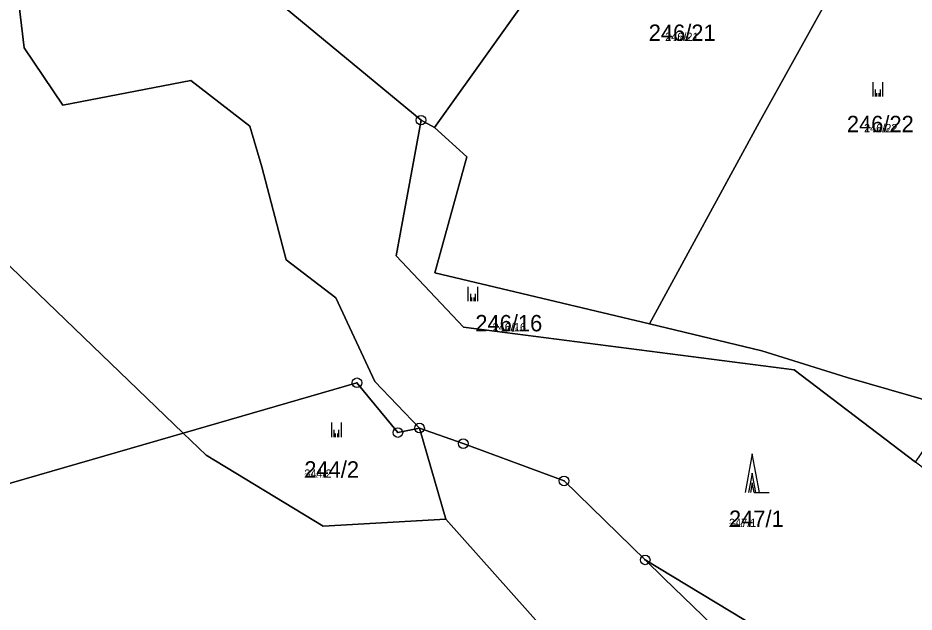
# Model space of a CAD drawing. Extents: x -759873 to -758487, y -975024 to -973516.
# Drawn here: x -759165.8 to -759072.7, y -974638.1 to -974576.4 of the extents above; entities that cross this region are included whole.
import ezdxf

# ---------------------------------------------------------------- set-up
doc = ezdxf.new("R2010")
doc.units = 0
for name, color, linetype in [('KAT_02_hranice parcel', 7, 'Continuous'), ('KAT_03_1000_čísla parcelní', 7, 'Continuous'), ('KAT_03_250_čísla parcelní', 7, 'Continuous'), ('KAT_03_500_čísla parcelní', 7, 'Continuous'), ('KAT_05_1000_značky kultur', 7, 'Continuous'), ('KAT_05_250_značky kultur', 7, 'Continuous'), ('KAT_05_500_značky kultur', 7, 'Continuous'), ('KAT_11_značky bodu BP', 7, 'Continuous'), ('KAT_14_plocha_pozemek', 7, 'Continuous')]:
    doc.layers.add(name, color=color, linetype=linetype)

msp = doc.modelspace()

# ---------------------------------------------------------------- linework, layer by layer
at = {"layer": 'KAT_02_hranice parcel'}
for p, q in [((-759123.88, -974586.97), (-759138.78, -974574.64)), ((-759122.47, -974587.73), (-759123.88, -974586.97)), ((-759181.41, -974628.97), (-759148.58, -974619.46)), ((-759121.31, -974628.39), (-759124.04, -974618.94))]:
    msp.add_line(p, q, dxfattribs=at)
for points in [[(-759124.04, -974618.94), (-759128.67, -974614.12), (-759132.72, -974605.42), (-759137.89, -974601.46), (-759140.41, -974591.83), (-759141.66, -974587.58), (-759147.81, -974582.84), (-759161.09, -974585.41), (-759165.12, -974579.47), (-759166.21, -974570.14), (-759161.85, -974571.03), (-759164.75, -974552.56), (-759173.97, -974541.64), (-759175.43, -974540.05), (-759178.37, -974531.68), (-759179.47, -974515.71), (-759177.07, -974506.79), (-759176.34, -974497.63), (-759172.37, -974482.45)], [(-759122.47, -974587.73), (-759110.32, -974570.69), (-759106.9, -974566.95), (-759100.94, -974559.67), (-759093.17, -974549.44), (-759087, -974539.27)], [(-759100.16, -974608.12), (-759088.78, -974587.22), (-759079.24, -974570.06), (-759074.96, -974563.7), (-759067.83, -974550.62)], [(-759217.96, -974564.68), (-759183.74, -974565.93), (-759174.05, -974595), (-759148.58, -974619.46)], [(-759072.53, -974622.47), (-759085.12, -974612.91), (-759119.49, -974608.48), (-759126.45, -974601.07), (-759123.88, -974586.97)], [(-759100.16, -974608.12), (-759122.45, -974602.82), (-759119.12, -974590.77), (-759122.47, -974587.73)], [(-759068.68, -974616.85), (-759079.63, -974613.7), (-759088.47, -974610.92), (-759100.16, -974608.12)], [(-759148.58, -974619.46), (-759130.54, -974614.24), (-759126.29, -974619.41), (-759124.04, -974618.94)], [(-759148.58, -974619.46), (-759146.2, -974621.75), (-759134.04, -974629.13), (-759121.31, -974628.39)], [(-759100.6, -974632.63), (-759109.03, -974624.43), (-759119.5, -974620.56), (-759124.04, -974618.94)], [(-759121.31, -974628.39), (-759107.72, -974643.63), (-759105.8, -974660.49), (-759087.3, -974693.73), (-759084.37, -974695.3)], [(-759100.6, -974632.63), (-759098.65, -974634.53), (-759078.54, -974653.94), (-759071.5, -974656.72), (-759062.41, -974666.25), (-759055.52, -974672.89), (-759051.77, -974677.63)], [(-759051.77, -974677.63), (-759055.66, -974671.34), (-759078.61, -974645.91), (-759100.6, -974632.63)]]:
    msp.add_lwpolyline(points, dxfattribs=at)
at = {"layer": 'KAT_05_1000_značky kultur'}
for p, q in [((-759076.921, -974584.53), (-759076.921, -974583.03)), ((-759075.92, -974584.53), (-759075.92, -974583.03)), ((-759118.981, -974605.77), (-759118.981, -974604.27)), ((-759117.98, -974605.77), (-759117.98, -974604.27)), ((-759133.161, -974619.88), (-759133.161, -974618.38)), ((-759132.16, -974619.88), (-759132.16, -974618.38)), ((-759089.48, -974621.62), (-759090.23, -974625.62)), ((-759088.73, -974625.62), (-759089.48, -974621.62)), ((-759088.73, -974625.62), (-759087.734, -974625.62))]:
    msp.add_line(p, q, dxfattribs=at)
at = {"layer": 'KAT_05_250_značky kultur'}
for p, q in [((-759076.538, -974584.53), (-759076.538, -974584.155)), ((-759076.287, -974584.53), (-759076.287, -974584.155)), ((-759118.598, -974605.77), (-759118.598, -974605.395)), ((-759118.348, -974605.77), (-759118.348, -974605.395)), ((-759132.778, -974619.88), (-759132.778, -974619.505)), ((-759132.527, -974619.88), (-759132.527, -974619.505)), ((-759089.48, -974624.62), (-759089.667, -974625.62)), ((-759089.292, -974625.62), (-759089.48, -974624.62)), ((-759089.292, -974625.62), (-759089.044, -974625.62))]:
    msp.add_line(p, q, dxfattribs=at)
at = {"layer": 'KAT_05_500_značky kultur'}
for p, q in [((-759076.666, -974584.53), (-759076.666, -974583.78)), ((-759076.165, -974584.53), (-759076.165, -974583.78)), ((-759118.726, -974605.77), (-759118.726, -974605.02)), ((-759118.225, -974605.77), (-759118.225, -974605.02)), ((-759132.905, -974619.88), (-759132.905, -974619.13)), ((-759132.405, -974619.88), (-759132.405, -974619.13)), ((-759089.48, -974623.62), (-759089.855, -974625.62)), ((-759089.105, -974625.62), (-759089.48, -974623.62)), ((-759089.105, -974625.62), (-759088.607, -974625.62))]:
    msp.add_line(p, q, dxfattribs=at)
at = {"layer": 'KAT_11_značky bodu BP'}
for centre, radius in [((-759123.88, -974586.97), 0.5), ((-759123.88, -974586.97), 0.0303), ((-759130.54, -974614.24), 0.5), ((-759130.54, -974614.24), 0.0303), ((-759124.04, -974618.94), 0.5), ((-759126.29, -974619.41), 0.5), ((-759126.29, -974619.41), 0.0303), ((-759124.04, -974618.94), 0.0303), ((-759119.5, -974620.56), 0.5), ((-759119.5, -974620.56), 0.0303), ((-759109.03, -974624.43), 0.5), ((-759109.03, -974624.43), 0.0303), ((-759100.6, -974632.63), 0.5), ((-759100.6, -974632.63), 0.0303)]:
    msp.add_circle(centre, radius, dxfattribs=at)
at = {"layer": 'KAT_14_plocha_pozemek'}
for points in [[(-759100.94, -974559.67), (-759093.17, -974549.44), (-759087, -974539.27), (-759103.43, -974529.17), (-759109.92, -974539.83), (-759120.96, -974554.48), (-759138.78, -974574.64), (-759123.88, -974586.97), (-759122.47, -974587.73), (-759110.32, -974570.69), (-759106.9, -974566.95)], [(-759067.83, -974550.62), (-759072.82, -974547.99), (-759087, -974539.27), (-759093.17, -974549.44), (-759100.94, -974559.67), (-759106.9, -974566.95), (-759110.32, -974570.69), (-759122.47, -974587.73), (-759119.12, -974590.77), (-759122.45, -974602.82), (-759100.16, -974608.12), (-759088.78, -974587.22), (-759079.24, -974570.06), (-759074.96, -974563.7)], [(-759053.94, -974586.07), (-759041.97, -974564.24), (-759067.83, -974550.62), (-759074.96, -974563.7), (-759079.24, -974570.06), (-759088.78, -974587.22), (-759100.16, -974608.12), (-759088.47, -974610.92), (-759079.63, -974613.7), (-759068.68, -974616.85), (-759056.36, -974598.66), (-759059.73, -974595.66)], [(-759148.58, -974619.46), (-759174.05, -974595), (-759183.74, -974565.93), (-759217.96, -974564.68), (-759215.84, -974572.78), (-759190.97, -974589.12), (-759179.03, -974595.95), (-759179.19, -974596.85), (-759181.67, -974625.03), (-759181.41, -974628.97)], [(-759088.47, -974610.92), (-759100.16, -974608.12), (-759122.45, -974602.82), (-759119.12, -974590.77), (-759122.47, -974587.73), (-759123.88, -974586.97), (-759126.45, -974601.07), (-759119.49, -974608.48), (-759085.12, -974612.91), (-759072.53, -974622.47), (-759068.68, -974616.85), (-759079.63, -974613.7)], [(-759134.04, -974629.13), (-759121.31, -974628.39), (-759124.04, -974618.94), (-759126.29, -974619.41), (-759130.54, -974614.24), (-759148.58, -974619.46), (-759146.2, -974621.75)], [(-759179.97, -974642.79), (-759172.86, -974648.93), (-759159.84, -974663.56), (-759149.76, -974675.44), (-759144.18, -974680.88), (-759136.32, -974697.59), (-759132.9, -974707), (-759084.37, -974695.3), (-759087.3, -974693.73), (-759105.8, -974660.49), (-759107.72, -974643.63), (-759121.31, -974628.39), (-759134.04, -974629.13), (-759146.2, -974621.75), (-759148.58, -974619.46), (-759181.41, -974628.97), (-759180.71, -974639.63)], [(-759050.14, -974687.05), (-759051.77, -974677.63), (-759055.52, -974672.89), (-759062.41, -974666.25), (-759071.5, -974656.72), (-759078.54, -974653.94), (-759098.65, -974634.53), (-759100.6, -974632.63), (-759109.03, -974624.43), (-759119.5, -974620.56), (-759124.04, -974618.94), (-759121.31, -974628.39), (-759107.72, -974643.63), (-759105.8, -974660.49), (-759087.3, -974693.73), (-759084.37, -974695.3)], [(-759055.66, -974671.34), (-759078.61, -974645.91), (-759100.6, -974632.63), (-759098.65, -974634.53), (-759078.54, -974653.94), (-759071.5, -974656.72), (-759062.41, -974666.25), (-759055.52, -974672.89), (-759051.77, -974677.63)]]:
    msp.add_lwpolyline(points, close=True, dxfattribs=at)
for points in [[(-758985.91, -974649.95), (-759011.32, -974639.13), (-759058.27, -974633.29), (-759072.53, -974622.47), (-759085.12, -974612.91), (-759119.49, -974608.48), (-759126.45, -974601.07), (-759123.88, -974586.97), (-759138.78, -974574.64), (-759149.95, -974565.4), (-759151.3, -974564.28), (-759155.66, -974538.03), (-759168.27, -974530.82)], [(-759174.05, -974595), (-759148.58, -974619.46), (-759130.54, -974614.24), (-759126.29, -974619.41), (-759124.04, -974618.94), (-759128.67, -974614.12), (-759132.72, -974605.42), (-759137.89, -974601.46), (-759140.41, -974591.83), (-759141.66, -974587.58), (-759147.81, -974582.84), (-759161.09, -974585.41), (-759165.12, -974579.47), (-759166.21, -974570.14), (-759161.85, -974571.03), (-759164.75, -974552.56), (-759173.97, -974541.64)], [(-759173.97, -974541.64), (-759164.75, -974552.56), (-759161.85, -974571.03), (-759166.21, -974570.14), (-759165.12, -974579.47), (-759161.09, -974585.41), (-759147.81, -974582.84), (-759141.66, -974587.58), (-759140.41, -974591.83), (-759137.89, -974601.46), (-759132.72, -974605.42), (-759128.67, -974614.12), (-759124.04, -974618.94), (-759119.5, -974620.56), (-759109.03, -974624.43), (-759100.6, -974632.63), (-759078.61, -974645.91)]]:
    msp.add_lwpolyline(points, dxfattribs=at)

# ---------------------------------------------------------------- texts
at = {"layer": 'KAT_03_1000_čísla parcelní'}
for s, p in [('246/21', (-759100.235, -974578.74)), ('246/22', (-759079.655, -974588.22)), ('246/16', (-759118.245, -974608.9)), ('244/2', (-759136.01, -974624.09)), ('247/1', (-759091.9, -974629.21))]:
    msp.add_text(s, height=1.7, dxfattribs=at).set_placement(p)
at = {"layer": 'KAT_03_250_čísla parcelní'}
for s, p in [('246/21', (-759097.676, -974578.74)), ('246/22', (-759076.979, -974588.22)), ('246/16', (-759115.562, -974608.9)), ('244/2', (-759136.01, -974624.09)), ('247/1', (-759091.9, -974629.21))]:
    msp.add_text(s, height=0.425, dxfattribs=at).set_placement(p)
at = {"layer": 'KAT_03_500_čísla parcelní'}
for s, p in [('246/21', (-759098.529, -974578.74)), ('246/22', (-759077.871, -974588.22)), ('246/16', (-759116.457, -974608.9)), ('244/2', (-759136.01, -974624.09)), ('247/1', (-759091.9, -974629.21))]:
    msp.add_text(s, height=0.85, dxfattribs=at).set_placement(p)

doc.saveas('drawing.dxf')
